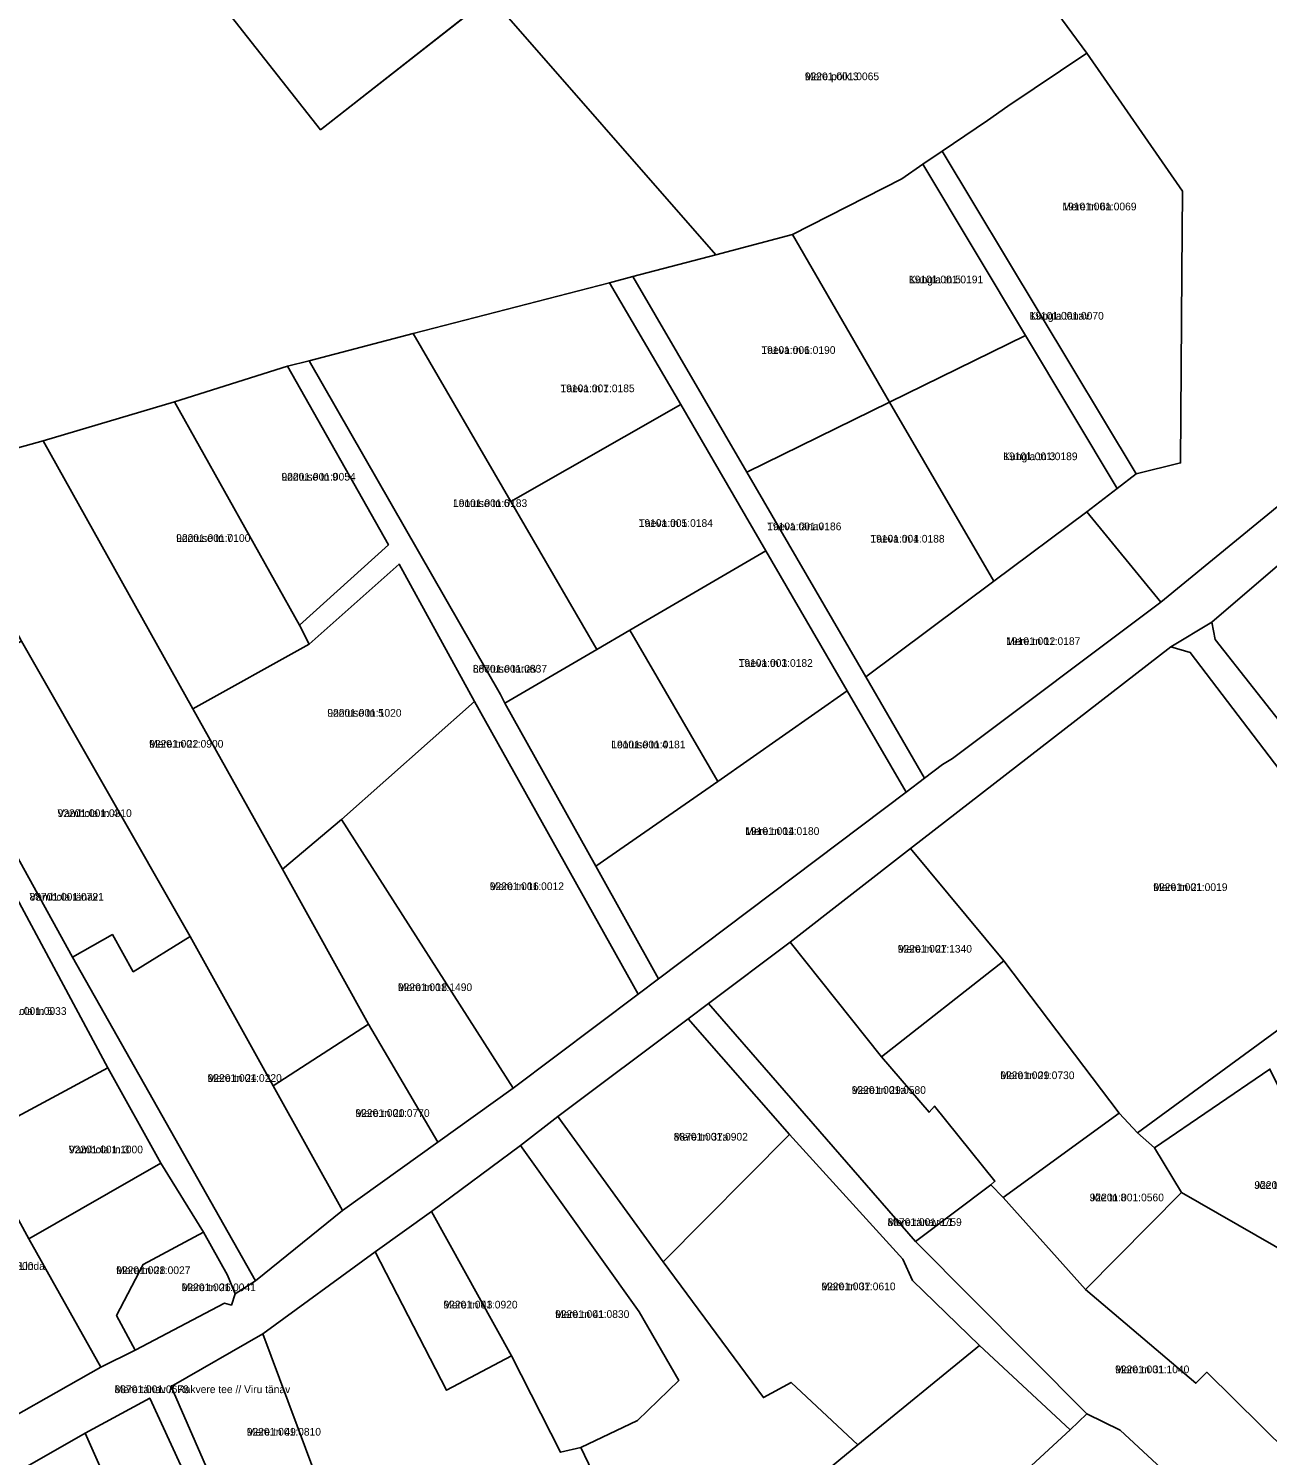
# Model space of a CAD drawing. Extents: x 601493 to 643081, y 6584980 to 6634019.
# Drawn here: x 610866.3 to 611108.4, y 6605975.5 to 6606254.3 of the extents above; entities that cross this region are included whole.
import ezdxf

# ---------------------------------------------------------------- set-up
doc = ezdxf.new("R2010")
doc.units = 0
for name, color, linetype in [('L_AADRESS', 7, 'Continuous'), ('PIIR', 7, 'Continuous'), ('TUNNUS', 7, 'Continuous')]:
    doc.layers.add(name, color=color, linetype=linetype)

msp = doc.modelspace()

# ---------------------------------------------------------------- linework, layer by layer
at = {"layer": 'PIIR'}
for points in [[(611073.07, 6606159.9), (611078.99, 6606164.44), (611082.73, 6606167.29), (611091.42, 6606169.43), (611091.64, 6606206.61), (611091.81, 6606222.53), (611073.07, 6606249.53), (611051.85, 6606278.36), (611112.41, 6606311.99), (611135.51, 6606313.25), (611230.04, 6606258.95), (611087.53, 6606142.22)], [(610892.42, 6606273.86), (610925.1, 6606300.11), (610933.65, 6606286.93), (610956.53, 6606260.54), (610923.34, 6606234.54)], [(611015.56, 6606214.09), (611000.6, 6606210.08), (610956.52, 6606260.54), (610987.18, 6606269.04), (611017.46, 6606276.26), (611051.83, 6606278.36), (611073.07, 6606249.53), (611057.65, 6606239.12), (611053.66, 6606236.37), (611044.79, 6606230.33), (611041.07, 6606227.79), (611036.96, 6606224.93)], [(611057.65, 6606239.12), (611073.07, 6606249.53), (611091.81, 6606222.53), (611091.64, 6606206.61), (611091.42, 6606169.43), (611082.73, 6606167.29), (611044.79, 6606230.33), (611053.66, 6606236.37)], [(611041.07, 6606227.79), (611044.79, 6606230.33), (611082.73, 6606167.29), (611078.99, 6606164.44), (611061.09, 6606194.33)], [(611034.55, 6606181.34), (611015.56, 6606214.09), (611036.96, 6606224.93), (611041.07, 6606227.79), (611061.09, 6606194.33)], [(611006.64, 6606167.63), (610984.4, 6606205.84), (611000.6, 6606210.08), (611015.56, 6606214.09), (611034.55, 6606181.34)], [(610960.54, 6606161.88), (610941.44, 6606194.71), (610979.84, 6606204.65), (610993.74, 6606180.87)], [(610993.74, 6606180.87), (610979.84, 6606204.65), (610984.4, 6606205.84), (611006.64, 6606167.63), (611029.92, 6606127.62), (611041.39, 6606107.84), (611037.78, 6606105.13), (611026.28, 6606124.9), (611010.35, 6606152.24)], [(610958.48, 6606124.19), (610921.1, 6606189.4), (610941.44, 6606194.71), (610960.54, 6606161.88), (610977.35, 6606133.01), (610959.35, 6606122.53)], [(611054.94, 6606146.37), (611034.55, 6606181.34), (611061.09, 6606194.33), (611078.99, 6606164.44), (611073.07, 6606159.9)], [(610894.82, 6606181.36), (610916.86, 6606188.35), (610936.61, 6606153.43), (610919.23, 6606137.71)], [(610919.23, 6606137.71), (610936.61, 6606153.43), (610916.86, 6606188.35), (610921.1, 6606189.4), (610958.48, 6606124.19), (610959.35, 6606122.53), (610977.16, 6606090.63), (610989.37, 6606068.62), (610985.41, 6606065.64), (610953.44, 6606122.82), (610938.68, 6606149.66), (610921.1, 6606134.04)], [(610894.82, 6606181.36), (610919.23, 6606137.71), (610921.1, 6606134.04), (610898.39, 6606121.37), (610869.16, 6606173.76)], [(611029.92, 6606127.62), (611006.64, 6606167.63), (611034.55, 6606181.34), (611054.94, 6606146.37)], [(610977.35, 6606133.01), (610960.54, 6606161.88), (610993.74, 6606180.87), (611010.35, 6606152.24), (610983.79, 6606136.76)], [(610846.99, 6606167.62), (610869.16, 6606173.76), (610898.39, 6606121.37), (610915.94, 6606090.06), (610932.72, 6606059.8), (610914.06, 6606047.72), (610897.86, 6606076.93), (610864.92, 6606134.63)], [(611098.2, 6606134.91), (611097.49, 6606138.32), (611128.64, 6606165.01), (611142.23, 6606147.83), (611138.3, 6606142.23), (611113.17, 6606115.93)], [(610822.31, 6606159.75), (610826.48, 6606161.35), (610846.04, 6606125.17), (610874.9, 6606072.86), (610910.64, 6606009.66), (610906.63, 6606007.12), (610905.17, 6606010.75), (610900.5, 6606019.13), (610892.16, 6606032.65), (610881.75, 6606051.23), (610862.99, 6606086.2), (610861.18, 6606089.63), (610848.28, 6606112.74), (610843.59, 6606121.03)], [(611041.39, 6606107.84), (611029.92, 6606127.62), (611054.94, 6606146.37), (611073.07, 6606159.9), (611087.53, 6606142.22), (611046.81, 6606111.72), (611044.88, 6606110.5)], [(611000.97, 6606107.21), (610983.79, 6606136.76), (611010.35, 6606152.24), (611026.28, 6606124.9)], [(610915.94, 6606090.06), (610898.39, 6606121.37), (610921.1, 6606134.04), (610938.68, 6606149.66), (610953.44, 6606122.82), (610927.42, 6606099.78)], [(610977.16, 6606090.63), (610959.35, 6606122.53), (610977.35, 6606133.01), (610983.79, 6606136.76), (611000.97, 6606107.21)], [(610864.92, 6606134.63), (610897.86, 6606076.93), (610886.74, 6606070.01), (610882.68, 6606077.29), (610874.9, 6606072.86), (610846.04, 6606125.17)], [(611089.51, 6606133.5), (611093.31, 6606132.38), (611133.53, 6606079.59), (611123.86, 6606068.45), (611083.02, 6606038.54), (611079.4, 6606042.41), (611056.85, 6606072.14), (611038.62, 6606094.13)], [(610927.42, 6606099.78), (610953.44, 6606122.82), (610985.41, 6606065.64), (610961, 6606047.3)], [(610989.37, 6606068.62), (610977.16, 6606090.63), (611000.97, 6606107.21), (611026.28, 6606124.9), (611037.78, 6606105.13)], [(610915.94, 6606090.06), (610927.42, 6606099.78), (610961, 6606047.3), (610946.26, 6606036.71), (610932.72, 6606059.8)], [(611015.12, 6606075.83), (611038.62, 6606094.13), (611056.85, 6606072.14), (611032.96, 6606053.39)], [(610862.99, 6606086.2), (610881.75, 6606051.23), (610855.71, 6606037.22), (610851.73, 6606043.82), (610844.96, 6606040.35), (610836.67, 6606071.59)], [(610882.68, 6606077.29), (610886.74, 6606070.01), (610897.86, 6606076.93), (610914.06, 6606047.72), (610927.64, 6606023.39), (610910.64, 6606009.66), (610874.9, 6606072.86)], [(611043.3, 6606043.79), (611055.13, 6606029.09), (611054.32, 6606028.38), (611039.61, 6606017.31), (610999.16, 6606063.8), (611015.12, 6606075.83), (611032.96, 6606053.39), (611042.27, 6606042.57)], [(611054.32, 6606028.38), (611055.13, 6606029.09), (611043.3, 6606043.79), (611042.27, 6606042.57), (611032.96, 6606053.39), (611056.85, 6606072.14), (611079.4, 6606042.41), (611056.76, 6606025.9)], [(610999.16, 6606063.8), (611039.61, 6606017.31), (611073.09, 6605983.62), (611069.86, 6605980.54), (611052.1, 6605997.02), (611039.01, 6606009.67), (611037.11, 6606013.85), (611014.98, 6606038.22), (610995.18, 6606060.82)], [(610914.06, 6606047.72), (610932.72, 6606059.8), (610946.26, 6606036.71), (610927.64, 6606023.39)], [(610969.72, 6606041.76), (610995.18, 6606060.82), (611014.98, 6606038.22), (610990.32, 6606013.33)], [(610855.71, 6606037.22), (610881.75, 6606051.23), (610892.16, 6606032.65), (610866.34, 6606017.87)], [(611086.3, 6606035.65), (611108.88, 6606051.01), (611122.9, 6606022.74), (611129, 6606026.64), (611139.71, 6606014.03), (611131.2, 6606004.19), (611091.61, 6606026.92)], [(610825.46, 6606030.33), (610844.96, 6606040.35), (610851.73, 6606043.82), (610855.71, 6606037.22), (610866.34, 6606017.87), (610880.44, 6605992.8), (610854.6, 6605978.18), (610851.32, 6605983.9), (610825.05, 6606029.69)], [(611056.76, 6606025.9), (611079.4, 6606042.41), (611083.02, 6606038.54), (611086.3, 6606035.65), (611091.61, 6606026.92), (611072.83, 6606007.94)], [(611009.9, 6605986.82), (610990.32, 6606013.33), (611014.98, 6606038.22), (611037.11, 6606013.85), (611039.01, 6606009.67), (611052.1, 6605997.02), (611028.31, 6605977.57), (611015.3, 6605989.8)], [(610960.68, 6605994.97), (610945.03, 6606023.2), (610962.39, 6606036.06), (610985.61, 6606003.59), (610993.35, 6605990.17), (610985.29, 6605982.34), (610974.24, 6605977.06), (610970.25, 6605976.15)], [(610866.34, 6606017.87), (610892.16, 6606032.65), (610900.5, 6606019.13), (610888.67, 6606012.86), (610883.5, 6606002.84), (610887.09, 6605996.1), (610880.44, 6605992.8)], [(611039.61, 6606017.31), (611054.32, 6606028.38), (611056.76, 6606025.9), (611072.83, 6606007.94), (611094.39, 6605989.62), (611096.54, 6605991.79), (611117.79, 6605970.79), (611120.89, 6605967.72), (611118.94, 6605965.75), (611110.9, 6605959.65), (611110.08, 6605958.56), (611107.28, 6605954.8), (611103.8, 6605958.04), (611079.61, 6605980.43), (611073.09, 6605983.62)], [(611117.79, 6605970.79), (611096.54, 6605991.79), (611094.39, 6605989.62), (611072.83, 6606007.94), (611091.61, 6606026.92), (611131.2, 6606004.19), (611144.02, 6605996.77), (611149.59, 6605993.54), (611143.6, 6605988.55), (611139.07, 6605984.99), (611134.22, 6605981.16), (611120.89, 6605967.72)], [(610947.98, 6605988.25), (610934.02, 6606015.29), (610945.03, 6606023.2), (610960.68, 6605994.97)], [(610906.63, 6606007.12), (610905.93, 6606004.89), (610904.56, 6606005.25), (610887.09, 6605996.1), (610883.5, 6606002.84), (610888.67, 6606012.86), (610900.5, 6606019.13), (610905.17, 6606010.75)], [(610912.09, 6605999.25), (610934.02, 6606015.29), (610947.98, 6605988.25), (610960.68, 6605994.97), (610970.25, 6605976.15), (610974.24, 6605977.06), (610989.72, 6605944.68), (610994.4, 6605934.72), (610991.63, 6605932.47), (610986.89, 6605929.07), (610985.82, 6605928.67), (610981.32, 6605927), (610975.14, 6605927.31), (610967.61, 6605928.55), (610961.67, 6605928.89), (610955.93, 6605928.5), (610953.77, 6605927.57), (610951.82, 6605934.68), (610938.78, 6605959.26), (610929.15, 6605955.05), (610923.67, 6605968.23)], [(610923.67, 6605968.23), (610906.68, 6605960.32), (610894.18, 6605989.02), (610912.09, 6605999.25)], [(611043.62, 6605956.34), (611036.45, 6605949.71), (611037.09, 6605954.97), (611034.31, 6605961.16), (611028.54, 6605963.01), (611022.85, 6605969.3), (611020.89, 6605971.5), (611028.31, 6605977.57), (611052.1, 6605997.02), (611069.86, 6605980.54)], [(610877.35, 6605979.85), (610889.96, 6605986.73), (610904.36, 6605955.48), (610890.78, 6605949.7)], [(611036.26, 6605948.17), (611036.45, 6605949.71), (611043.62, 6605956.34), (611069.86, 6605980.54), (611073.09, 6605983.62), (611079.61, 6605980.43), (611103.8, 6605958.04), (611107.28, 6605954.8), (611107.25, 6605954.76), (611105.98, 6605952.13), (611102.16, 6605942.64), (611097.93, 6605934.81), (611092.15, 6605928.73), (611085.81, 6605925.29), (611080.7, 6605923.59), (611074.1, 6605924.42), (611065.24, 6605927.41), (611057.51, 6605931.02), (611051.32, 6605933.19), (611044.1, 6605934.12), (611039.04, 6605934.45), (611035.43, 6605936.1), (611033.47, 6605938.89), (611033.99, 6605942.7)], [(610877.35, 6605979.85), (610890.78, 6605949.7), (610896.22, 6605937.94), (610883.9, 6605931.88), (610863.17, 6605921.48), (610842.57, 6605960.03)]]:
    msp.add_lwpolyline(points, close=True, dxfattribs=at)
for points in [[(610892.42, 6606273.86), (610923.34, 6606234.54), (610956.52, 6606260.54), (611000.6, 6606210.08), (610984.4, 6606205.84), (610979.84, 6606204.65), (610941.44, 6606194.71), (610921.1, 6606189.4), (610916.86, 6606188.35), (610894.82, 6606181.36), (610869.16, 6606173.76), (610846.99, 6606167.62), (610826.48, 6606161.35), (610822.31, 6606159.75), (610794.83, 6606151.7), (610763.18, 6606142.56), (610707.99, 6606126.26), (610712.68, 6606117.8), (610709.28, 6606115.98), (610663.8, 6606090.91), (610657.56, 6606113.43)], [(610854.6, 6605978.18), (610880.44, 6605992.8), (610887.09, 6605996.1), (610904.56, 6606005.25), (610905.93, 6606004.89), (610906.63, 6606007.12), (610910.64, 6606009.66), (610927.64, 6606023.39), (610946.26, 6606036.71), (610961, 6606047.3), (610985.41, 6606065.64), (610989.37, 6606068.62), (611037.78, 6606105.13), (611041.39, 6606107.84), (611044.88, 6606110.5), (611046.81, 6606111.72), (611087.53, 6606142.22), (611230.04, 6606258.95)], [(611128.64, 6606165.01), (611097.49, 6606138.32), (611089.51, 6606133.5), (611038.62, 6606094.13), (611015.12, 6606075.83), (610999.16, 6606063.8), (610995.18, 6606060.82), (610969.72, 6606041.76), (610962.39, 6606036.06), (610945.03, 6606023.2), (610934.02, 6606015.29), (610912.09, 6605999.25), (610894.18, 6605989.02), (610906.68, 6605960.32), (610908.5, 6605957.28), (610904.36, 6605955.48), (610889.96, 6605986.73), (610877.35, 6605979.85), (610842.57, 6605960.03)], [(611133.53, 6606079.59), (611093.31, 6606132.38), (611089.51, 6606133.5), (611097.49, 6606138.32), (611098.2, 6606134.91), (611113.17, 6606115.93)], [(611108.88, 6606051.01), (611086.3, 6606035.65), (611083.02, 6606038.54), (611123.86, 6606068.45)], [(610989.72, 6605944.68), (610974.24, 6605977.06), (610985.29, 6605982.34), (610993.35, 6605990.17), (610985.61, 6606003.59), (610962.39, 6606036.06), (610969.72, 6606041.76), (610990.32, 6606013.33), (611009.9, 6605986.82), (611015.3, 6605989.8), (611028.31, 6605977.57), (611020.89, 6605971.5)]]:
    msp.add_lwpolyline(points, dxfattribs=at)

# ---------------------------------------------------------------- texts
at = {"layer": 'L_AADRESS'}
for s, p in [('Mere põik 3', (611017.99, 6606244.22)), ('Mere tn 6a', (611068.3, 6606218.79)), ('Kungla tn 5', (611038.33, 6606204.53)), ('Kungla tänav', (611061.9, 6606197.44)), ('Taeva tn 6', (611009.47, 6606190.74)), ('Taeva tn 7', (610970.22, 6606183.26)), ('Kungla tn 3', (611056.77, 6606169.98)), ('Lootuse tn 9', (610915.71, 6606165.99)), ('Lootuse tn 6', (610949.23, 6606160.83)), ('Taeva tn 5', (610985.52, 6606156.94)), ('Taeva tänav', (611010.62, 6606156.29)), ('Lootuse tn 7', (610895.13, 6606154.01)), ('Taeva tn 4', (611030.79, 6606153.88)), ('Mere tn 12', (611057.32, 6606133.87)), ('Taeva tn 3', (611005.04, 6606129.6)), ('Lootuse tänav', (610953.11, 6606128.48)), ('Lootuse tn 5', (610924.67, 6606119.86)), ('Mere tn 22', (610889.86, 6606113.81)), ('Lootuse tn 4', (610980.16, 6606113.68)), ('Vambola tn 4', (610871.95, 6606100.26)), ('Mere tn 14', (611006.32, 6606096.76)), ('Mere tn 16', (610956.41, 6606085.98)), ('Mere tn 21', (611086.07, 6606085.81)), ('Vambola tänav', (610866.48, 6606083.92)), ('Mere tn 27', (611036.14, 6606073.76)), ('Mere tn 18', (610938.47, 6606066.25)), ('Vambola tn 5', (610859.21, 6606061.6)), ('Mere tn 29', (611056.18, 6606049.05)), ('Mere tn 24', (610901.27, 6606048.51)), ('Mere tn 29a', (611027.14, 6606046.17)), ('Mere tn 20', (610930.16, 6606041.67)), ('Mere tn 37a', (610992.35, 6606037.04)), ('Vambola tn 3', (610874.14, 6606034.55)), ('Jõe tn 6', (611105.84, 6606027.6)), ('Jõe tn 8', (611073.65, 6606025.18)), ('Mere tänav L1', (611034.14, 6606020.36)), ('Mere tn 30 // Linda', (610852.74, 6606011.78)), ('Mere tn 28', (610883.42, 6606010.96)), ('Mere tn 26', (610896.2, 6606007.62)), ('Mere tn 37', (611021.21, 6606007.8)), ('Mere tn 43', (610947.35, 6606004.24)), ('Mere tn 41', (610969.19, 6606002.39)), ('Mere tn 31', (611078.62, 6605991.59)), ('Mere tänav // Rakvere tee // Viru tänav', (610883.09, 6605987.7)), ('Mere tn 49', (610908.93, 6605979.4))]:
    msp.add_text(s, height=1.5, dxfattribs=at).set_placement(p)
at = {"layer": 'TUNNUS'}
for s, p in [('92201:001:0065', (611017.99, 6606244.22)), ('19101:001:0069', (611068.3, 6606218.79)), ('19101:001:0191', (611038.33, 6606204.53)), ('19101:001:0070', (611061.9, 6606197.44)), ('19101:001:0190', (611009.47, 6606190.74)), ('19101:001:0185', (610970.22, 6606183.26)), ('19101:001:0189', (611056.77, 6606169.98)), ('92201:001:0054', (610915.71, 6606165.99)), ('19101:001:0183', (610949.23, 6606160.83)), ('19101:001:0184', (610985.52, 6606156.94)), ('19101:001:0186', (611010.62, 6606156.29)), ('92201:001:0100', (610895.13, 6606154.01)), ('19101:001:0188', (611030.79, 6606153.88)), ('19101:001:0187', (611057.32, 6606133.87)), ('19101:001:0182', (611005.04, 6606129.6)), ('88701:001:0837', (610953.11, 6606128.48)), ('92201:001:1020', (610924.67, 6606119.86)), ('92201:001:0900', (610889.86, 6606113.81)), ('19101:001:0181', (610980.16, 6606113.68)), ('92201:001:0310', (610871.95, 6606100.26)), ('19101:001:0180', (611006.32, 6606096.76)), ('92201:001:0012', (610956.41, 6606085.98)), ('92201:001:0019', (611086.07, 6606085.81)), ('88701:001:0721', (610866.48, 6606083.92)), ('92201:001:1340', (611036.14, 6606073.76)), ('92201:001:1490', (610938.47, 6606066.25)), ('92201:001:0033', (610859.21, 6606061.6)), ('92201:001:0730', (611056.18, 6606049.05)), ('92201:001:0220', (610901.27, 6606048.51)), ('92201:001:0580', (611027.14, 6606046.17)), ('92201:001:0770', (610930.16, 6606041.67)), ('88701:001:0902', (610992.35, 6606037.04)), ('92201:001:1000', (610874.14, 6606034.55)), ('92201:001:0042', (611105.84, 6606027.6)), ('92201:001:0560', (611073.65, 6606025.18)), ('88701:001:0759', (611034.14, 6606020.36)), ('92201:001:0800', (610852.74, 6606011.78)), ('92201:001:0027', (610883.42, 6606010.96)), ('92201:001:0041', (610896.2, 6606007.62)), ('92201:001:0610', (611021.21, 6606007.8)), ('92201:001:0920', (610947.35, 6606004.24)), ('92201:001:0830', (610969.19, 6606002.39)), ('92201:001:1040', (611078.62, 6605991.59)), ('88701:001:0678', (610883.09, 6605987.7)), ('92201:001:0810', (610908.93, 6605979.4))]:
    msp.add_text(s, height=1.5, dxfattribs=at).set_placement(p)

doc.saveas('drawing.dxf')
